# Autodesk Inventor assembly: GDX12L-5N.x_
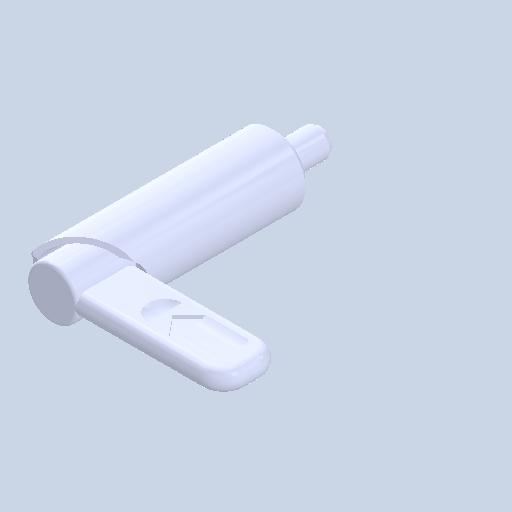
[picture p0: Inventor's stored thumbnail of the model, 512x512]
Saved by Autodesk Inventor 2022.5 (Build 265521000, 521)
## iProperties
Created: 2024-06
Part Number: GDX12L-5N.x_
Document SubType Name: Assembly
Designer: ImaoCorp
Author: ImaoCorp
Sending System: SOLIDWORKS 2022-2022290
MC: AMD64
MC_MODEL: Intel64 Family 6 Model 60 Stepping 3, GenuineIntel
OS: Windows_NT
FRU: Parasolid Version 33.1, build 260,  4-25-2022
FORMAT: text
GUISE: transmit
KEY: FILEGDX12L-5N.x_t
DATE: Wed Jun 12 09:31:40 2024
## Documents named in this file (3)
- Y:\5.更新分\2024年対応\xxxx_GDX\データ_imao品番\gdx12l-5n\GDX12L-5N.x_.iam
- Y:\5.更新分\2024年対応\xxxx_GDX\データ_imao品番\gdx12l-5n\GDX12L-5N_01.ipt
- Y:\5.更新分\2024年対応\xxxx_GDX\データ_imao品番\gdx12l-5n\GDX12L-5N_02.ipt
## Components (2 placed, 2 different names)
1. GDX12L-5N_01
2. GDX12L-5N_02
